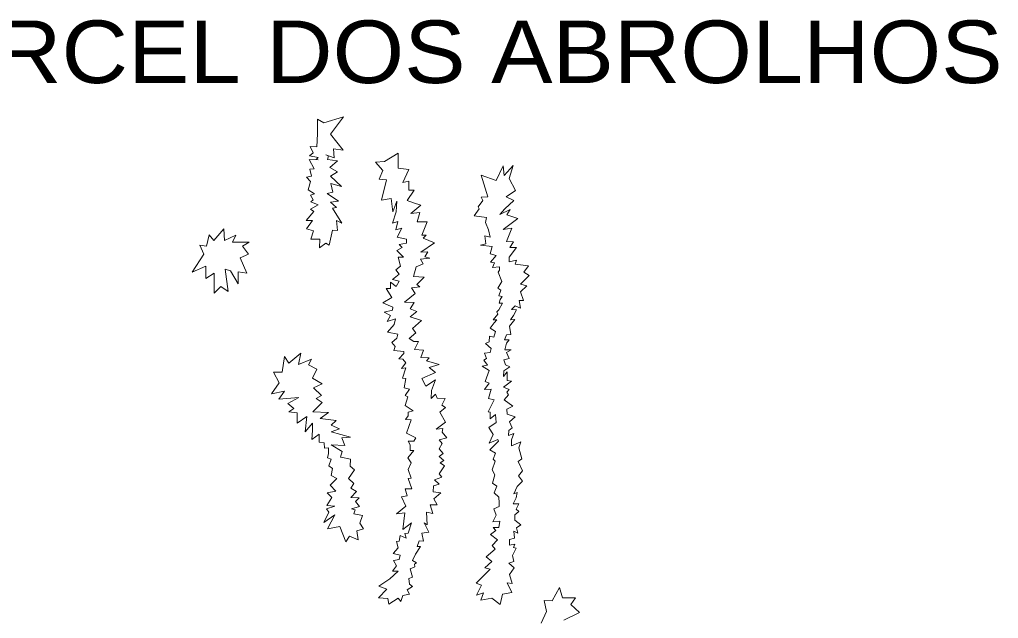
# Model space of a CAD drawing. Extents: x 47169 to 972804, y 7447977 to 9608469.
# Drawn here: x 532696 to 542865, y 8014469 to 8020692 of the extents above; entities that cross this region are included whole.
import ezdxf

# ---------------------------------------------------------------- set-up
doc = ezdxf.new("R2010")
doc.units = 0
doc.header["$LTSCALE"] = 270
doc.layers.add('1', color=7, linetype='Continuous', lineweight=13)
doc.layers.add('3', color=7, linetype='Continuous')

msp = doc.modelspace()

# ---------------------------------------------------------------- linework, layer by layer
at = {"layer": '1'}
for points in [[(536059.4, 8019680.9), (535926.7, 8019500.8), (536056.7, 8019335.7), (535957.1, 8019350.3), (535964.4, 8019254), (535878.6, 8019287.4), (535906.2, 8019275.1), (535893.4, 8019238.7), (535998.2, 8019224.1), (535918.7, 8019155.6), (536000.1, 8019109), (535925.9, 8019066), (536040.1, 8018956.3), (535928.9, 8018989.7), (535948.9, 8018898.9), (535890.6, 8018885.7), (536010.2, 8018804.7), (535925.4, 8018793.8), (535986.8, 8018740.6), (535946.5, 8018730.7), (536044.7, 8018577.9), (535986.5, 8018605.6), (535996.9, 8018499.4), (535948.2, 8018505), (535911.9, 8018346.9), (535879.1, 8018370.2), (535813.3, 8018319.4), (535813.5, 8018411.2), (535721.3, 8018411.4), (535750.1, 8018497.6), (535676, 8018517.7), (535737.6, 8018603.9), (535674, 8018604), (535752.6, 8018697.9), (535716.6, 8018721.2), (535798.2, 8018766.4), (535719.9, 8018799.7), (535747.5, 8018817.4), (535716.9, 8018866.1), (535760.3, 8018881.5), (535694.7, 8018921.5), (535718.2, 8019007.7), (535677, 8019054.3), (535727.8, 8019066.4), (535710, 8019138.3), (535756.6, 8019140.4), (535705.9, 8019236.8), (535799.1, 8019234.4), (535776.9, 8019238.9), (535797, 8019259.9), (535706, 8019277.7), (535744.2, 8019307.5), (535715.7, 8019374), (535784.5, 8019369.4), (535790.1, 8019503.3), (535790.3, 8019655.9), (535855.9, 8019618.2)], [(534833.2, 8018099.9), (534861.4, 8017866.4), (534785.2, 8017919.6), (534716.3, 8017848.9), (534716.7, 8018056.9), (534629.7, 8018001.8), (534629.9, 8018131.2), (534487.9, 8018067.3), (534610, 8018252.9), (534566.8, 8018349.3), (534637.7, 8018337), (534666.5, 8018456.4), (534715.1, 8018395.5), (534817, 8018517), (534824.2, 8018395.3), (534940.8, 8018450.4), (534907.9, 8018377.4), (535080.5, 8018379.3), (535011.6, 8018338.5), (535075, 8018254.3), (534986, 8018216.9), (535057.7, 8018056.3), (534965.6, 8018069.8), (534965.3, 8017944.7), (534887.2, 8018082.1)], [(535617.5, 8017226.6), (535594, 8017107.2), (535729.7, 8017163.4), (535695.7, 8017104.8), (535784.6, 8017059.3), (535738.9, 8016967.5), (535840.4, 8016906.5), (535749.3, 8016865.7), (535832.8, 8016784.8), (535778.7, 8016753.9), (535840.1, 8016712.9), (535743.5, 8016614.6), (535906.6, 8016608.7), (535819.6, 8016548), (535984.8, 8016524.5), (535933.9, 8016477), (536020.7, 8016438.2), (535933.8, 8016408.4), (536134.9, 8016351.6), (536042.7, 8016344.1), (536073.3, 8016267.7), (535933.5, 8016273.5), (536047.8, 8016202.4), (536029.7, 8016146), (536031.8, 8016146), (536133.4, 8016122.6), (536131.2, 8016051.8), (536174.5, 8016014.1), (536112.9, 8015924.6), (536168.9, 8015871.4), (536138.2, 8015822.8), (536196.3, 8015787.3), (536138, 8015724.3), (536224.8, 8015720.8), (536186.6, 8015683.3), (536226.8, 8015632.3), (536143.1, 8015607), (536181.2, 8015597), (536168.4, 8015556.1), (536257.3, 8015538.2), (536231.7, 8015457.5), (536269.7, 8015398.8), (536200.9, 8015381.2), (536213.4, 8015287.2), (536122.4, 8015324.9), (536084.2, 8015266.4), (536023.1, 8015424.7), (535893.8, 8015399.5), (535972.4, 8015546.5), (535857.9, 8015464.8), (535908.9, 8015574.2), (535883.6, 8015607.5), (535972.6, 8015635), (535886.8, 8015642.9), (535939.9, 8015726.9), (535891.3, 8015775.7), (535980.3, 8015793.2), (535922.2, 8015854.2), (535991.1, 8015922.6), (535932.9, 8015955.9), (535947.9, 8016026.7), (535909.8, 8016054.4), (535933.2, 8016123), (535895.2, 8016136.3), (535904.8, 8016181.7), (535904.9, 8016242.5), (535864.6, 8016238.2), (535859.4, 8016293.5), (535808.6, 8016299.1), (535808.8, 8016383.2), (535732.4, 8016326.9), (535737.9, 8016423.2), (535738, 8016497.3), (535663.7, 8016408.9), (535679.9, 8016568.2), (535580.2, 8016497.6), (535580.4, 8016604.9), (535494.6, 8016615), (535545.5, 8016650.3), (535484.2, 8016703.5), (535596.6, 8016764.2), (535390, 8016749.1), (535446.3, 8016830.9), (535311.8, 8016803.4), (535393.5, 8016917.2), (535332.3, 8017026.9), (535423.4, 8017028.9), (535449.1, 8017189.3), (535492.4, 8017120.6)]]:
    msp.add_lwpolyline(points, close=True, dxfattribs=at)
for points in [[(536619.6, 8018429.7), (536667.4, 8018523.6), (536603.8, 8018506), (536624.1, 8018594.5), (536571.1, 8018576.9), (536607.3, 8018694.1), (536615, 8018805.8), (536574.5, 8018694.2), (536556.8, 8018833.6), (536457.2, 8018816.1), (536506.3, 8019027.3), (536430, 8019031.9), (536468.3, 8019123.6), (536392.2, 8019210.1), (536486.5, 8019217.7), (536628.6, 8019303.7)], [(536628.6, 8019303.7), (536628.3, 8019146.6), (536740.6, 8019133.1), (536676.7, 8018998.2), (536740.3, 8019013.6), (536740.2, 8018919.6), (536795.2, 8018919.5), (536724.1, 8018813.4), (536787.6, 8018787.8), (536863.8, 8018764.4), (536759.8, 8018678.3), (536854.1, 8018685.9), (536825.3, 8018589.7), (536930.2, 8018589.5), (536873.8, 8018452.4), (536919.3, 8018452.3), (536888.6, 8018419.2), (537006, 8018372.5), (536866, 8018274.3), (536937, 8018278.6), (536906.2, 8018225.5), (536959.1, 8018213.3), (536860.6, 8018203.5), (536890.2, 8018154.8), (536817, 8018123.9), (536788.3, 8018022.2), (536898.4, 8018015.4), (536824.1, 8017939.1), (536854.8, 8017915.9), (536767.9, 8017902.7), (536805.9, 8017845.1), (536694.6, 8017755.7), (536796.2, 8017753.3), (536754.8, 8017687), (536823.6, 8017657), (536752.5, 8017602.9), (536872.1, 8017565.1), (536777.7, 8017483.4), (536812.6, 8017438), (536743.6, 8017377.2), (536792.3, 8017346.2), (536841, 8017346.1), (536797.4, 8017263.2), (536891.7, 8017257.5), (536862.9, 8017181.2), (536951.9, 8017176.6), (536924.3, 8017145.7), (537053.4, 8017107.8), (536951.7, 8017077), (537018.3, 8017023.8), (536875.2, 8016963.2), (536916.4, 8016881.3), (537018.2, 8016947.5), (536974.6, 8016838), (536971.2, 8016753.9), (537017.9, 8016800.3), (537034.8, 8016757.1), (537116.3, 8016753.7), (537083.4, 8016685.1), (537121.4, 8016659.6), (537063.1, 8016612.1), (537121.2, 8016506.9), (537024.7, 8016436.3), (537093.5, 8016441.7), (537085, 8016406.3), (537135.7, 8016344.2), (537055.1, 8016326.7), (537084.7, 8016286.8), (537055, 8016232.7), (537095.1, 8016181.7), (537054.8, 8016151.9), (537102.4, 8016110.9), (537064.2, 8016085.5), (537109.7, 8016055.5), (537054.5, 8015971.5), (537084.1, 8015936.1), (537007.8, 8015910.8), (537053.2, 8015864.2), (536994.9, 8015846.6), (536992.7, 8015785.8), (537071.1, 8015775.7), (537000, 8015711.6), (537032.7, 8015650.7), (536961.8, 8015650.9), (536989.1, 8015560.1), (536923.5, 8015572.4), (536930.6, 8015442.9), (536897.9, 8015462.9), (536948.5, 8015364.3), (536874.3, 8015354.5), (536892.2, 8015272.6), (536846.7, 8015274.9), (536826.4, 8015217.4), (536859.3, 8015217.4), (536810.4, 8015135.6), (536777.4, 8015072.6), (536817.7, 8015047), (536797.5, 8015031.6), (536802.7, 8015003.9), (536751.9, 8014986.3), (536777.1, 8014896.7)], [(537492.5, 8019076.4), (537648.1, 8019019.6), (537721.4, 8019172.2), (537729.7, 8019070.4), (537823.1, 8019176.4), (537782.6, 8019039.3), (537848, 8018915.2), (537749.4, 8018851.3), (537829.8, 8018813.5), (537738.6, 8018725.2), (537685.5, 8018666.6), (537791.5, 8018719.5), (537756.5, 8018663.2), (537870.8, 8018625.3), (537718.1, 8018511.7), (537809.2, 8018523.7), (537755.9, 8018384.4), (537826.9, 8018382), (537790.8, 8018323.4), (537859.6, 8018323.3), (537783.2, 8018223.9), (537783.1, 8018173), (537859.4, 8018190.5), (537844.5, 8018150.7), (537984.2, 8018131.7), (537935.4, 8018068.7), (537991.5, 8018031), (537900.2, 8017943.7), (537965.8, 8017923.7), (537900.1, 8017863), (537929.5, 8017774.4), (537887.2, 8017771.2), (537898.7, 8017692.6), (537845.7, 8017715.9), (537807.6, 8017680.6), (537858.4, 8017675), (537827.6, 8017616.4), (537796.8, 8017571.1), (537840.2, 8017575.4), (537787.1, 8017504.7), (537799.6, 8017420.6), (537754.1, 8017416.3), (537732.8, 8017365.4), (537781.5, 8017365.3), (537753.9, 8017330), (537737.9, 8017261.4), (537804.6, 8017261.3), (537755.8, 8017232.6), (537783.3, 8017169.5), (537728.2, 8017156.3), (537745, 8017103.2), (537788.4, 8017083.2), (537727.9, 8017042.4), (537724.7, 8016981.5), (537762.9, 8017030.1), (537762.7, 8016942.7), (537806.1, 8016936), (537724.4, 8016872), (537782.7, 8016846.4), (537757.2, 8016818.8), (537775.1, 8016791.1), (537731.6, 8016740.3), (537820.4, 8016673.8), (537756.8, 8016642.9), (537762, 8016592), (537845.7, 8016564.2), (537787.3, 8016513.4), (537814.7, 8016450.3), (537779.7, 8016422.7), (537776.4, 8016368.5), (537830.5, 8016389.4), (537804.9, 8016325.3), (537806.9, 8016264.4), (537903.4, 8016305.2), (537883.2, 8016241), (537913.7, 8016129.2), (537875.5, 8016099.4), (537920.8, 8016003.1), (537880.5, 8015952.3), (537920.6, 8015895.8), (537864.4, 8015840.5), (537831.4, 8015764.3), (537864.3, 8015778.6), (537854.6, 8015723.3), (537823.8, 8015660.3), (537884.2, 8015659.1), (537854.4, 8015603.8), (537881.9, 8015580.5), (537841.6, 8015545.2), (537841.5, 8015489.9), (537904.9, 8015441.1), (537858.3, 8015410.2), (537870.9, 8015354.8), (537830.7, 8015374.8), (537837.9, 8015301.8), (537785, 8015290.8), (537784.8, 8015230), (537841, 8015240.9), (537828.2, 8015207.8), (537853.6, 8015200), (537815.3, 8015123.7)], [(537567.6, 8018506.4), (537537.1, 8018582.8), (537547.8, 8018633.7), (537418.6, 8018653.9), (537471.7, 8018725.7), (537461.1, 8018745.6), (537507.8, 8018811.9), (537489.9, 8018847.3), (537560.9, 8018851.6), (537492.5, 8019076.4)], [(536777.1, 8014896.7), (536741.1, 8014884.5), (536746.3, 8014823.7), (536776.9, 8014800.4), (536723.9, 8014767.3), (536746.1, 8014721.9), (536677.2, 8014706.5), (536657, 8014645.7), (536629.5, 8014681.2), (536533.1, 8014618.3), (536522.6, 8014675.8), (536426.2, 8014683.8), (536512.2, 8014773.2), (536428.6, 8014803.2), (536540.9, 8014881.6), (536630.1, 8014961.1), (536568.6, 8014961.2), (536610, 8015016.5), (536581.5, 8015069.6), (536637.7, 8015080.6), (536650.5, 8015125.9), (536576.4, 8015143.8), (536630.5, 8015202.3), (536610.5, 8015268.7), (536640.2, 8015273.1), (536648.7, 8015331.7), (536712.2, 8015303.9), (536699.6, 8015351.5), (536732.4, 8015354.8), (536768.7, 8015463.1), (536676.4, 8015392.5), (536696.8, 8015565.1), (536613.2, 8015557.5), (536707.6, 8015637), (536662.2, 8015731.1), (536722.6, 8015743.1), (536702.6, 8015817.3), (536769.3, 8015817.2), (536733.5, 8015923.5), (536764.2, 8015925.6), (536731.6, 8016015.3), (536764.5, 8016086), (536728.6, 8016137), (536792.3, 8016215.4), (536752.1, 8016215.5), (536754.3, 8016274.2), (536732.1, 8016312.9), (536792.5, 8016312.8), (536813.7, 8016344.8), (536716.4, 8016395.9), (536765.4, 8016533), (536703.9, 8016536.5), (536732.6, 8016574), (536732.7, 8016612.7), (536783.5, 8016624.8), (536702.1, 8016681.4), (536727.7, 8016772.1), (536702.3, 8016785.4), (536745.8, 8016851.7), (536691.8, 8016864), (536710, 8016963.5), (536675.1, 8016965.8), (536708.1, 8017072), (536662.6, 8017067.6), (536708.2, 8017126.2), (536677.6, 8017161.6), (536634.2, 8017166.1), (536688.3, 8017222.5), (536688.3, 8017242.4), (536583.5, 8017252.5), (536596.3, 8017293.4), (536563.5, 8017336.7), (536616.6, 8017383), (536625.1, 8017422.8), (536518.2, 8017444), (536587.2, 8017522.5), (536602.1, 8017583.3), (536515.2, 8017555.8), (536549.2, 8017616.6), (536482.5, 8017652.1), (536571.5, 8017671.9), (536574.8, 8017705), (536467.9, 8017748.4), (536562.3, 8017802.4), (536504.2, 8017898.8), (536549.7, 8017896.5), (536549.8, 8017961.8), (536608, 8017918.5), (536638.8, 8017974.9), (536570, 8017992.7), (536639, 8018045.7), (536606.2, 8018091.1), (536653.9, 8018129.8), (536628.7, 8018223.8), (536682.7, 8018223.7), (536616.1, 8018292.5), (536670.2, 8018322.2), (536639.5, 8018355.5), (536715.8, 8018368.6), (536715.9, 8018411.8), (536619.6, 8018429.7)], [(537815.3, 8015123.7), (537832.2, 8015059.5), (537777.1, 8015041.9), (537835.2, 8014994.2), (537786.4, 8014925.7), (537811.6, 8014831.6), (537760.8, 8014839.5), (537811.4, 8014737.6), (537711.9, 8014720.1), (537689.4, 8014612.8), (537602.7, 8014681.5), (537488.3, 8014659.6), (537517, 8014734.8), (537442.9, 8014709.5), (537493.9, 8014814.5), (537441, 8014834.5), (537583.2, 8014981.4), (537530.2, 8014994.8), (537601.3, 8015059.9), (537543.2, 8015111), (537637.6, 8015190.4), (537603.8, 8015228.1), (537660, 8015284.4), (537589.2, 8015342.1), (537642.2, 8015382.9), (537616.8, 8015414), (537676.1, 8015413.9), (537683.7, 8015479.1), (537612.7, 8015472.6), (537647.8, 8015543.4), (537622.5, 8015609.8), (537678.7, 8015631.8), (537678.7, 8015670.5), (537673.6, 8015729.2), (537626, 8015774.6), (537653.6, 8015843.2), (537610.3, 8015873.1), (537633.8, 8015962.7), (537605.3, 8016013.7), (537636.1, 8016102.1), (537616.1, 8016123.2), (537639.5, 8016186.2), (537581.3, 8016219.5), (537670.4, 8016311.1), (537665.2, 8016328.9), (537572.9, 8016290.3), (537616.6, 8016382.1), (537571.2, 8016453), (537647.5, 8016503.7), (537640.2, 8016590), (537584, 8016544.8), (537586.3, 8016611.1), (537564, 8016615.6), (537624.6, 8016740.5), (537566.4, 8016756.1), (537595.2, 8016852.3), (537526.3, 8016846.9), (537574.1, 8016915.4), (537533.9, 8016931), (537574.4, 8017044.9), (537501.4, 8017091.5), (537557.6, 8017101.3), (537519.5, 8017154.5), (537547.1, 8017169.9), (537527.1, 8017225.3), (537583.2, 8017232.9), (537596, 8017273.9), (537537.9, 8017327.1), (537572.8, 8017344.7), (537576.1, 8017401.1), (537621.7, 8017393.3), (537639.8, 8017449.7), (537585.8, 8017485.2), (537627.2, 8017540.4), (537652.7, 8017573.6), (537614.6, 8017571.4), (537665.5, 8017632.2), (537652.9, 8017655.5), (537675.2, 8017675.3), (537713.4, 8017743.8), (537678.5, 8017743.9), (537688.1, 8017784.8), (537708.2, 8017814.7), (537673.3, 8017820.2), (537695.7, 8017881.1), (537662.9, 8017901), (537706.4, 8017969.6), (537666.4, 8018067), (537681.2, 8018086.9), (537681.3, 8018122.3), (537610.3, 8018114.7), (537628.4, 8018165.5), (537587.1, 8018171.2), (537648.7, 8018239.6), (537585.2, 8018257.5), (537605.4, 8018333.8), (537483.7, 8018346.2), (537539.8, 8018361.5), (537529.4, 8018445.6), (537585.5, 8018432.3), (537567.6, 8018506.4)], [(538115.8, 8014419.5), (538170, 8014541), (538147, 8014657.3), (538228.5, 8014652.7), (538305, 8014791.9)], [(538305, 8014791.9), (538337.6, 8014682.3), (538472.1, 8014682.1), (538424.3, 8014613.6), (538513.1, 8014532.6), (538349.9, 8014451.1)]]:
    msp.add_lwpolyline(points, dxfattribs=at)

# ---------------------------------------------------------------- texts
at = {"layer": '3', "width": 1.1}
msp.add_text('PARCEL DOS ABROLHOS', height=650.1, dxfattribs=at).set_placement((531165, 8020032))

doc.saveas('drawing.dxf')
